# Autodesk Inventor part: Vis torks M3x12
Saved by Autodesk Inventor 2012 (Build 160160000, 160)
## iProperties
Created: 2012-11
Part Number: Vis torks M3x12
Material: Default
Document SubType Name: Modeling
Designer: Administrateur
Density: 1 g/cm^3
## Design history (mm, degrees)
node "Vis torks M3x121"
node "Vis torks M3x12"
node "Base1"
